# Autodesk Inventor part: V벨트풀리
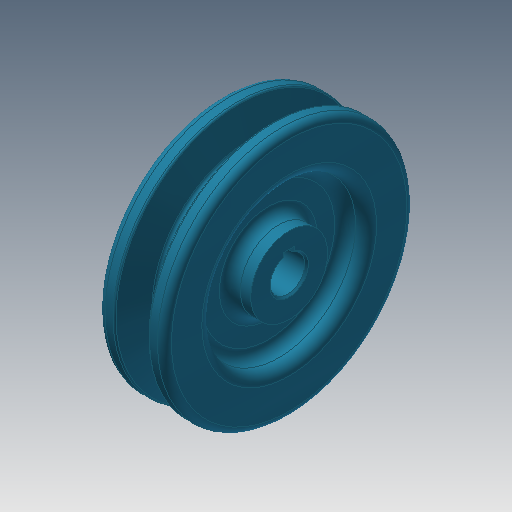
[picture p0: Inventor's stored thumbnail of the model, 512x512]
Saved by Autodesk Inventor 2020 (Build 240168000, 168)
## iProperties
Created: 2015-11
Part Number: V벨트풀리
Material: 강철, 탄소
Document SubType Name: Modeling
Designer: mduedu
Density: 7.87 g/cm^3
Mass: 380.065 g
Surface Area: 160.69 cm^2
Volume: 48.2929 cm^3
Appearance: 터키옥색
Author: mduedu
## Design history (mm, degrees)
sketch "스케치1"
  geometry: L1 (-9.5, 0)-(9.5, 0); L2 (0, 0)-(0, 35.7); L3 (-4.825, 35.7)-(-9.5, 35.7); L4 (-9.5, 35.7)-(-9.5, 0); L5 (0, 26.7)-(-2.074, 26.7); L6 (-2.074, 26.7)-(-4.825, 35.7); L7 (4.825, 35.7)-(9.5, 35.7); L8 (9.5, 35.7)-(9.5, 0); L9 (0, 26.7)-(2.074, 26.7); L10 (2.074, 26.7)-(4.825, 35.7); L11 (-9.5, 33)-(9.5, 33); 3 further points
  constraints: 22 end point, 7 point on line, 4 perpendicular, 3 symmetric about line, 1 coincident, 1 horizontal, 1 horizontal alignment, 1 midpoint, 1 vertical
  dimensions: "d0" = 19 distance of L1.start L1.end; "d2" = 71.4 diameter of L2.end L1 (derived); "d3" = 34 deg angle of L10 L6; "d4" = 6.3 distance between parallel lines of L11 L9; "d5" = 2.7 distance between parallel lines of L7 L11; "d6" = 8 distance of point (4, 33) point (-4, 33); "d7" = 66 diameter of L11 L1
revolve "회전1" sketch "스케치1" stored, may be unused: angle "d8" = 90 deg
sketch "스케치2"
  geometry: C1 r 22 at (0, 0); C2 r 11 at (0, 0); 1 further point
  constraints: 2 centre point, 2 coincident
  dimensions: "d9" = 44 diameter of C1; "d10" = 22 diameter of C2
extrude "돌출1" cut sketch "스케치2" distance "d11" = 6; taper "d12" = 0 deg
fillet "모깎기1" dims "d13" = 3
fillet "모깎기2" dims "d14" = 3
fillet "모깎기3" dims "d15" = 1, "d16" = 0.5, "d17" = 2
hole "구멍1" diameter "d20" = 10; stored, may be unused: countersink angle "d24" = 90 deg, drill point angle "d26" = 118 deg; dims "d18" = 10, "d19" = 10, "d21" = 6, "d22" = 4, "d23" = 2, "d25" = 8
sketch "스케치3"
  geometry: L1 (-1.5, 0)-(1.5, 0); L2 (1.5, 0)-(1.5, 6.4); L3 (1.5, 6.4)-(-1.5, 6.4); L4 (-1.5, 6.4)-(-1.5, 0); 2 further points
  constraints: 8 end point, 2 parallel, 1 coincident, 1 horizontal, 1 midpoint, 1 perpendicular
  dimensions: "d27" = 3 distance of L2.end L3.end; "d29" = 6.4 distance of L3.end L1.start
extrude "돌출2" cut sketch "스케치3" extent not by distance; stored distance "d30" = 6; taper "d31" = 0 deg
chamfer "모따기1" distance "d32" = 0.5; stored, may be unused: second distance "d33" = 2, angle "d34" = 45 deg
node "솔리드1"
mirror "대칭1"
